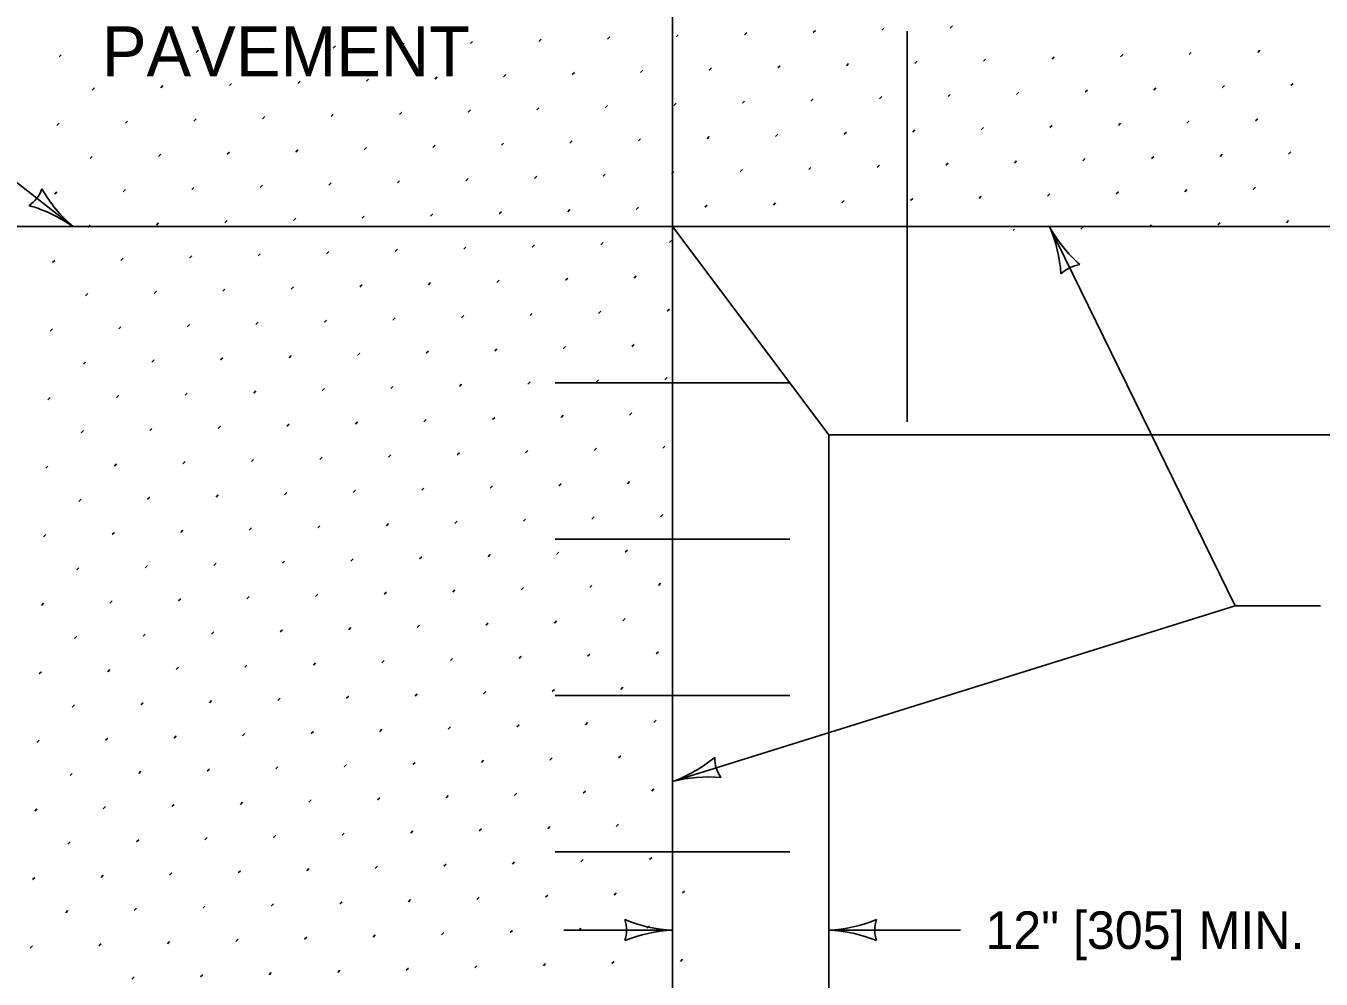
# Model space of a CAD drawing. Extents: x 49991.4 to 50021, y 49987.6 to 50011.4.
# Drawn here: x 50001.323 to 50003.394, y 49990.601 to 49992.125 of the extents above; entities that cross this region are included whole.
import ezdxf

# ---------------------------------------------------------------- set-up
doc = ezdxf.new("R2010")
doc.units = 0
for name, color, linetype in [('Level 1', 7, 'Continuous'), ('Level 10', 7, 'Continuous'), ('Level 2', 7, 'Continuous'), ('Level 3', 7, 'Continuous'), ('Level 4', 7, 'Continuous')]:
    doc.layers.add(name, color=color, linetype=linetype)

msp = doc.modelspace()

# ---------------------------------------------------------------- linework, layer by layer
at = {"layer": 'Level 1'}
for p, q in [((50002.3571, 49991.8039), (50002.3571, 49992.8039)), ((50001.1571, 49991.8039), (50002.3571, 49991.8039)), ((50006.1071, 49991.8039), (50002.3571, 49991.8039)), ((50002.3571, 49991.8039), (50002.3571, 49988.8039)), ((50002.3571, 49991.8039), (50002.6071, 49991.4706)), ((50002.6071, 49991.4706), (50002.6071, 49989.1372)), ((50002.6071, 49991.4706), (50005.8571, 49991.4706))]:
    msp.add_line(p, q, dxfattribs=at)
at = {"layer": 'Level 10'}
for p, q in [((50000.7223, 49992.3318), (50001.3986, 49991.8039)), ((50002.582, 49992.114), (50002.5856, 49992.1175)), ((50002.6916, 49992.1176), (50002.6952, 49992.1211)), ((50002.8013, 49992.1211), (50002.8048, 49992.1246)), ((50002.034, 49992.0963), (50002.0375, 49992.0998)), ((50002.1436, 49992.0998), (50002.1471, 49992.1034)), ((50002.2532, 49992.1034), (50002.2567, 49992.1069)), ((50002.3628, 49992.1069), (50002.3664, 49992.1105)), ((50002.4724, 49992.1105), (50002.476, 49992.114)), ((50001.3763, 49992.075), (50001.3799, 49992.0786)), ((50001.486, 49992.0786), (50001.4895, 49992.0821)), ((50001.5956, 49992.0821), (50001.5991, 49992.0857)), ((50001.7052, 49992.0857), (50001.7087, 49992.0892)), ((50001.8148, 49992.0892), (50001.8183, 49992.0928)), ((50001.9244, 49992.0928), (50001.9279, 49992.0963)), ((50003.0735, 49992.0752), (50003.077, 49992.0787)), ((50003.1831, 49992.0787), (50003.1866, 49992.0822)), ((50003.2927, 49992.0822), (50003.2963, 49992.0858)), ((50002.4159, 49992.0539), (50002.4194, 49992.0574)), ((50002.5255, 49992.0574), (50002.529, 49992.061)), ((50002.6351, 49992.061), (50002.6386, 49992.0645)), ((50002.7447, 49992.0645), (50002.7482, 49992.0681)), ((50002.8543, 49992.0681), (50002.8578, 49992.0716)), ((50002.9639, 49992.0716), (50002.9674, 49992.0751)), ((50001.7582, 49992.0326), (50001.7617, 49992.0362)), ((50001.8678, 49992.0362), (50001.8713, 49992.0397)), ((50001.9774, 49992.0397), (50001.981, 49992.0433)), ((50002.087, 49992.0433), (50002.0906, 49992.0468)), ((50002.1966, 49992.0468), (50002.2002, 49992.0503)), ((50002.3062, 49992.0504), (50002.3098, 49992.0539)), ((50001.4294, 49992.022), (50001.4329, 49992.0255)), ((50001.539, 49992.0256), (50001.5425, 49992.0291)), ((50001.6486, 49992.0291), (50001.6521, 49992.0326)), ((50002.7977, 49992.0115), (50002.8012, 49992.015)), ((50002.9073, 49992.015), (50002.9109, 49992.0186)), ((50003.0169, 49992.0186), (50003.0205, 49992.0221)), ((50003.1265, 49992.0221), (50003.1301, 49992.0257)), ((50003.2361, 49992.0257), (50003.2397, 49992.0292)), ((50003.3458, 49992.0292), (50003.3493, 49992.0327)), ((50002.1401, 49991.9902), (50002.1436, 49991.9938)), ((50002.2497, 49991.9938), (50002.2532, 49991.9973)), ((50002.3593, 49991.9973), (50002.3628, 49992.0009)), ((50002.4689, 49992.0009), (50002.4724, 49992.0044)), ((50002.5785, 49992.0044), (50002.582, 49992.0079)), ((50002.6881, 49992.0079), (50002.6916, 49992.0115)), ((50001.4824, 49991.969), (50001.4859, 49991.9725)), ((50001.592, 49991.9725), (50001.5956, 49991.9761)), ((50001.7016, 49991.9761), (50001.7052, 49991.9796)), ((50001.8112, 49991.9796), (50001.8148, 49991.9831)), ((50001.9208, 49991.9831), (50001.9244, 49991.9867)), ((50002.0305, 49991.9867), (50002.034, 49991.9902)), ((50003.1796, 49991.9691), (50003.1831, 49991.9726)), ((50003.2892, 49991.9726), (50003.2927, 49991.9762)), ((50001.3728, 49991.9654), (50001.3763, 49991.969)), ((50002.6315, 49991.9514), (50002.6351, 49991.9549)), ((50002.7411, 49991.9549), (50002.7447, 49991.9584)), ((50002.8507, 49991.9585), (50002.8543, 49991.962)), ((50002.9604, 49991.962), (50002.9639, 49991.9655)), ((50003.07, 49991.9655), (50003.0735, 49991.9691)), ((50001.9739, 49991.9301), (50001.9774, 49991.9337)), ((50002.0835, 49991.9337), (50002.087, 49991.9372)), ((50002.1931, 49991.9372), (50002.1966, 49991.9407)), ((50002.3027, 49991.9407), (50002.3062, 49991.9443)), ((50002.4123, 49991.9443), (50002.4158, 49991.9478)), ((50002.5219, 49991.9478), (50002.5255, 49991.9514)), ((50001.4258, 49991.9124), (50001.4294, 49991.9159)), ((50001.5354, 49991.9159), (50001.539, 49991.9195)), ((50001.6451, 49991.9195), (50001.6486, 49991.923)), ((50001.7547, 49991.923), (50001.7582, 49991.9266)), ((50001.8643, 49991.9266), (50001.8678, 49991.9301)), ((50003.0134, 49991.909), (50003.0169, 49991.9125)), ((50003.123, 49991.9125), (50003.1265, 49991.916)), ((50003.2326, 49991.9161), (50003.2361, 49991.9196)), ((50003.3422, 49991.9196), (50003.3457, 49991.9231)), ((50002.3557, 49991.8877), (50002.3593, 49991.8912)), ((50002.4653, 49991.8913), (50002.4689, 49991.8948)), ((50002.575, 49991.8948), (50002.5785, 49991.8983)), ((50002.6846, 49991.8983), (50002.6881, 49991.9019)), ((50002.7942, 49991.9019), (50002.7977, 49991.9054)), ((50002.9038, 49991.9054), (50002.9073, 49991.909)), ((50001.6981, 49991.8665), (50001.7016, 49991.87)), ((50001.8077, 49991.87), (50001.8112, 49991.8735)), ((50001.9173, 49991.8735), (50001.9208, 49991.8771)), ((50002.0269, 49991.8771), (50002.0304, 49991.8806)), ((50002.1365, 49991.8806), (50002.1401, 49991.8842)), ((50002.2461, 49991.8842), (50002.2497, 49991.8877)), ((50001.3693, 49991.8558), (50001.3728, 49991.8594)), ((50001.4789, 49991.8594), (50001.4824, 49991.8629)), ((50001.5885, 49991.8629), (50001.592, 49991.8664)), ((50002.7376, 49991.8453), (50002.7411, 49991.8488)), ((50002.8472, 49991.8488), (50002.8507, 49991.8524)), ((50002.9568, 49991.8524), (50002.9603, 49991.8559)), ((50003.0664, 49991.8559), (50003.07, 49991.8595)), ((50003.176, 49991.8595), (50003.1796, 49991.863)), ((50003.2856, 49991.863), (50003.2892, 49991.8666)), ((50002.0799, 49991.8241), (50002.0835, 49991.8276)), ((50002.1896, 49991.8276), (50002.1931, 49991.8311)), ((50002.2992, 49991.8311), (50002.3027, 49991.8347)), ((50002.4088, 49991.8347), (50002.4123, 49991.8382)), ((50002.5184, 49991.8382), (50002.5219, 49991.8418)), ((50002.628, 49991.8418), (50002.6315, 49991.8453)), ((50001.5319, 49991.8063), (50001.5354, 49991.8099)), ((50001.6415, 49991.8099), (50001.645, 49991.8134)), ((50001.7511, 49991.8134), (50001.7547, 49991.817)), ((50001.8607, 49991.817), (50001.8643, 49991.8205)), ((50001.9703, 49991.8205), (50001.9739, 49991.824)), ((50003.2291, 49991.8064), (50003.2326, 49991.81)), ((50003.3387, 49991.81), (50003.3422, 49991.8135)), ((50001.4223, 49991.8028), (50001.4258, 49991.8063)), ((50002.9019, 49991.7974), (50002.9038, 49991.7994)), ((50003.0098, 49991.7994), (50003.0134, 49991.8029)), ((50003.1195, 49991.8029), (50003.123, 49991.8064)), ((50001.9138, 49991.7639), (50001.9173, 49991.7675)), ((50002.0234, 49991.7675), (50002.0269, 49991.771)), ((50002.133, 49991.771), (50002.1365, 49991.7746)), ((50002.2426, 49991.7746), (50002.2461, 49991.7781)), ((50002.3522, 49991.7781), (50002.3557, 49991.7816)), ((50001.3657, 49991.7462), (50001.3693, 49991.7498)), ((50001.4753, 49991.7498), (50001.4789, 49991.7533)), ((50001.5849, 49991.7533), (50001.5885, 49991.7568)), ((50001.6945, 49991.7568), (50001.6981, 49991.7604)), ((50001.8041, 49991.7604), (50001.8077, 49991.7639)), ((50002.2956, 49991.7215), (50002.2992, 49991.7251)), ((50001.638, 49991.7003), (50001.6415, 49991.7038)), ((50001.7476, 49991.7038), (50001.7511, 49991.7073)), ((50001.8572, 49991.7074), (50001.8607, 49991.7109)), ((50001.9668, 49991.7109), (50001.9703, 49991.7144)), ((50002.0764, 49991.7144), (50002.0799, 49991.718)), ((50002.186, 49991.718), (50002.1895, 49991.7215)), ((50001.4187, 49991.6932), (50001.4223, 49991.6967)), ((50001.5284, 49991.6967), (50001.5319, 49991.7003)), ((50002.1294, 49991.6614), (50002.133, 49991.6649)), ((50002.239, 49991.665), (50002.2426, 49991.6685)), ((50002.3486, 49991.6685), (50002.3522, 49991.672)), ((50001.4718, 49991.6402), (50001.4753, 49991.6437)), ((50001.5814, 49991.6437), (50001.5849, 49991.6472)), ((50001.691, 49991.6472), (50001.6945, 49991.6508)), ((50001.8006, 49991.6508), (50001.8041, 49991.6543)), ((50001.9102, 49991.6543), (50001.9138, 49991.6579)), ((50002.0198, 49991.6579), (50002.0234, 49991.6614)), ((50001.3622, 49991.6366), (50001.3657, 49991.6401)), ((50001.8536, 49991.5977), (50001.8572, 49991.6013)), ((50001.9632, 49991.6013), (50001.9668, 49991.6048)), ((50002.0729, 49991.6048), (50002.0764, 49991.6084)), ((50002.1825, 49991.6084), (50002.186, 49991.6119)), ((50002.2921, 49991.6119), (50002.2956, 49991.6155)), ((50001.4152, 49991.5836), (50001.4187, 49991.5871)), ((50001.5248, 49991.5871), (50001.5283, 49991.5907)), ((50001.6344, 49991.5907), (50001.638, 49991.5942)), ((50001.744, 49991.5942), (50001.7476, 49991.5977)), ((50002.2355, 49991.5553), (50002.239, 49991.5589)), ((50002.3451, 49991.5589), (50002.3486, 49991.5624)), ((50001.5778, 49991.5341), (50001.5814, 49991.5376)), ((50001.6875, 49991.5376), (50001.691, 49991.5412)), ((50001.7971, 49991.5412), (50001.8006, 49991.5447)), ((50001.9067, 49991.5447), (50001.9102, 49991.5483)), ((50002.0163, 49991.5483), (50002.0198, 49991.5518)), ((50002.1259, 49991.5518), (50002.1294, 49991.5553)), ((50001.3586, 49991.527), (50001.3622, 49991.5305)), ((50001.4682, 49991.5305), (50001.4718, 49991.5341)), ((50002.0693, 49991.4952), (50002.0728, 49991.4988)), ((50002.1789, 49991.4988), (50002.1825, 49991.5023)), ((50002.2885, 49991.5023), (50002.2921, 49991.5058)), ((50001.4117, 49991.474), (50001.4152, 49991.4775)), ((50001.5213, 49991.4775), (50001.5248, 49991.481)), ((50001.6309, 49991.4811), (50001.6344, 49991.4846)), ((50001.7405, 49991.4846), (50001.744, 49991.4881)), ((50001.8501, 49991.4881), (50001.8536, 49991.4917)), ((50001.9597, 49991.4917), (50001.9632, 49991.4952)), ((50001.7935, 49991.4316), (50001.7971, 49991.4351)), ((50001.9031, 49991.4351), (50001.9067, 49991.4386)), ((50002.0127, 49991.4386), (50002.0163, 49991.4422)), ((50002.1223, 49991.4422), (50002.1259, 49991.4457)), ((50002.232, 49991.4457), (50002.2355, 49991.4493)), ((50002.3416, 49991.4493), (50002.3451, 49991.4528)), ((50001.3551, 49991.4174), (50001.3586, 49991.4209)), ((50001.4647, 49991.4209), (50001.4682, 49991.4245)), ((50001.5743, 49991.4245), (50001.5778, 49991.428)), ((50001.6839, 49991.428), (50001.6874, 49991.4316)), ((50002.1754, 49991.3892), (50002.1789, 49991.3927)), ((50002.285, 49991.3927), (50002.2885, 49991.3962)), ((50001.6273, 49991.3714), (50001.6309, 49991.375)), ((50001.7369, 49991.375), (50001.7405, 49991.3785)), ((50001.8466, 49991.3785), (50001.8501, 49991.3821)), ((50001.9562, 49991.3821), (50001.9597, 49991.3856)), ((50002.0658, 49991.3856), (50002.0693, 49991.3892)), ((50001.4081, 49991.3644), (50001.4117, 49991.3679)), ((50001.5177, 49991.3679), (50001.5213, 49991.3714)), ((50002.0092, 49991.329), (50002.0127, 49991.3326)), ((50002.1188, 49991.3326), (50002.1223, 49991.3361)), ((50002.2284, 49991.3361), (50002.2319, 49991.3397)), ((50002.338, 49991.3397), (50002.3416, 49991.3432)), ((50001.3515, 49991.3078), (50001.3551, 49991.3113)), ((50001.4612, 49991.3113), (50001.4647, 49991.3149)), ((50001.5708, 49991.3149), (50001.5743, 49991.3184)), ((50001.6804, 49991.3184), (50001.6839, 49991.3219)), ((50001.79, 49991.322), (50001.7935, 49991.3255)), ((50001.8996, 49991.3255), (50001.9031, 49991.329)), ((50001.7334, 49991.2654), (50001.7369, 49991.2689)), ((50001.843, 49991.2689), (50001.8465, 49991.2725)), ((50001.9526, 49991.2725), (50001.9562, 49991.276)), ((50002.0622, 49991.276), (50002.0658, 49991.2795)), ((50002.1718, 49991.2795), (50002.1754, 49991.2831)), ((50002.2814, 49991.2831), (50002.285, 49991.2866)), ((50001.4046, 49991.2548), (50001.4081, 49991.2583)), ((50001.5142, 49991.2583), (50001.5177, 49991.2618)), ((50001.6238, 49991.2618), (50001.6273, 49991.2654)), ((50002.2249, 49991.2265), (50002.2284, 49991.2301)), ((50002.3345, 49991.2301), (50002.338, 49991.2336)), ((50001.5672, 49991.2053), (50001.5708, 49991.2088)), ((50001.6768, 49991.2088), (50001.6804, 49991.2123)), ((50001.7864, 49991.2123), (50001.79, 49991.2159)), ((50001.896, 49991.2159), (50001.8996, 49991.2194)), ((50002.0057, 49991.2194), (50002.0092, 49991.223)), ((50002.1153, 49991.223), (50002.1188, 49991.2265)), ((50001.348, 49991.1982), (50001.3515, 49991.2017)), ((50001.4576, 49991.2017), (50001.4611, 49991.2053)), ((50003.2566, 49991.1975), (50003.393, 49991.1975)), ((50001.9491, 49991.1629), (50001.9526, 49991.1664)), ((50002.0587, 49991.1664), (50002.0622, 49991.1699)), ((50002.1683, 49991.1699), (50002.1718, 49991.1735)), ((50002.2779, 49991.1735), (50002.2814, 49991.177)), ((50001.401, 49991.1451), (50001.4046, 49991.1487)), ((50001.5106, 49991.1487), (50001.5142, 49991.1522)), ((50001.6203, 49991.1522), (50001.6238, 49991.1558)), ((50001.7299, 49991.1558), (50001.7334, 49991.1593)), ((50001.8395, 49991.1593), (50001.843, 49991.1628)), ((50002.3309, 49991.1205), (50002.3345, 49991.124)), ((50001.6733, 49991.0992), (50001.6768, 49991.1027)), ((50001.7829, 49991.1027), (50001.7864, 49991.1063)), ((50001.8925, 49991.1063), (50001.896, 49991.1098)), ((50002.0021, 49991.1098), (50002.0056, 49991.1134)), ((50002.1117, 49991.1134), (50002.1153, 49991.1169)), ((50002.2213, 49991.1169), (50002.2249, 49991.1204)), ((50001.3445, 49991.0886), (50001.348, 49991.0921)), ((50001.4541, 49991.0921), (50001.4576, 49991.0956)), ((50001.5637, 49991.0957), (50001.5672, 49991.0992)), ((50002.1648, 49991.0603), (50002.1683, 49991.0639)), ((50002.2744, 49991.0639), (50002.2779, 49991.0674)), ((50001.5071, 49991.0391), (50001.5106, 49991.0426)), ((50001.6167, 49991.0426), (50001.6202, 49991.0462)), ((50001.7263, 49991.0462), (50001.7299, 49991.0497)), ((50001.8359, 49991.0497), (50001.8395, 49991.0532)), ((50001.9455, 49991.0532), (50001.9491, 49991.0568)), ((50002.0551, 49991.0568), (50002.0587, 49991.0603)), ((50001.3975, 49991.0355), (50001.401, 49991.0391)), ((50001.889, 49990.9967), (50001.8925, 49991.0002)), ((50001.9986, 49991.0002), (50002.0021, 49991.0037)), ((50002.1082, 49991.0038), (50002.1117, 49991.0073)), ((50002.2178, 49991.0073), (50002.2213, 49991.0108)), ((50002.3274, 49991.0108), (50002.3309, 49991.0144)), ((50001.3409, 49990.979), (50001.3445, 49990.9825)), ((50001.4505, 49990.9825), (50001.4541, 49990.986)), ((50001.5601, 49990.986), (50001.5637, 49990.9896)), ((50001.6697, 49990.9896), (50001.6733, 49990.9931)), ((50001.7794, 49990.9931), (50001.7829, 49990.9967)), ((50002.2708, 49990.9543), (50002.2744, 49990.9578)), ((50001.7228, 49990.9366), (50001.7263, 49990.9401)), ((50001.8324, 49990.9401), (50001.8359, 49990.9436)), ((50001.942, 49990.9436), (50001.9455, 49990.9472)), ((50002.0516, 49990.9472), (50002.0551, 49990.9507)), ((50002.1612, 49990.9507), (50002.1647, 49990.9543)), ((50001.3939, 49990.9259), (50001.3975, 49990.9295)), ((50001.5036, 49990.9295), (50001.5071, 49990.933)), ((50001.6132, 49990.933), (50001.6167, 49990.9365)), ((50002.1046, 49990.8941), (50002.1082, 49990.8977)), ((50002.2142, 49990.8977), (50002.2178, 49990.9012)), ((50002.3239, 49990.9012), (50002.3274, 49990.9048)), ((50001.447, 49990.8729), (50001.4505, 49990.8764)), ((50001.5566, 49990.8764), (50001.5601, 49990.88)), ((50001.6662, 49990.88), (50001.6697, 49990.8835)), ((50001.7758, 49990.8835), (50001.7793, 49990.8871)), ((50001.8854, 49990.8871), (50001.889, 49990.8906)), ((50001.995, 49990.8906), (50001.9986, 49990.8941)), ((50001.3374, 49990.8693), (50001.3409, 49990.8729)), ((50001.8288, 49990.8305), (50001.8324, 49990.834)), ((50001.9385, 49990.834), (50001.942, 49990.8376)), ((50002.0481, 49990.8376), (50002.0516, 49990.8411)), ((50002.1577, 49990.8411), (50002.1612, 49990.8447)), ((50002.2673, 49990.8447), (50002.2708, 49990.8482)), ((50001.3904, 49990.8163), (50001.3939, 49990.8199)), ((50001.5, 49990.8199), (50001.5036, 49990.8234)), ((50001.6096, 49990.8234), (50001.6132, 49990.8269)), ((50001.7192, 49990.8269), (50001.7228, 49990.8305)), ((50002.3203, 49990.7916), (50002.3238, 49990.7952)), ((50001.6627, 49990.7704), (50001.6662, 49990.7739)), ((50001.7723, 49990.7739), (50001.7758, 49990.7774)), ((50001.8819, 49990.7775), (50001.8854, 49990.781)), ((50001.9915, 49990.781), (50001.995, 49990.7845)), ((50002.1011, 49990.7845), (50002.1046, 49990.7881)), ((50002.2107, 49990.7881), (50002.2142, 49990.7916)), ((50001.3338, 49990.7597), (50001.3374, 49990.7633)), ((50001.4434, 49990.7633), (50001.447, 49990.7668)), ((50001.553, 49990.7668), (50001.5566, 49990.7704)), ((50002.0445, 49990.728), (50002.0481, 49990.7315)), ((50002.1541, 49990.7315), (50002.1577, 49990.735)), ((50002.2637, 49990.735), (50002.2673, 49990.7386)), ((50002.3733, 49990.7386), (50002.3761, 49990.7413)), ((50001.3869, 49990.7067), (50001.3904, 49990.7102)), ((50001.4965, 49990.7103), (50001.5, 49990.7138)), ((50001.6061, 49990.7138), (50001.6096, 49990.7173)), ((50001.7157, 49990.7173), (50001.7192, 49990.7209)), ((50001.8253, 49990.7209), (50001.8288, 49990.7244)), ((50001.9349, 49990.7244), (50001.9384, 49990.728)), ((50001.7687, 49990.6643), (50001.7723, 49990.6678)), ((50001.8783, 49990.6678), (50001.8819, 49990.6714)), ((50001.9879, 49990.6714), (50001.9915, 49990.6749)), ((50002.0975, 49990.6749), (50002.1011, 49990.6785)), ((50002.2072, 49990.6785), (50002.2107, 49990.682)), ((50002.3168, 49990.682), (50002.3203, 49990.6856)), ((50001.3303, 49990.6501), (50001.3338, 49990.6537)), ((50001.4399, 49990.6537), (50001.4434, 49990.6572)), ((50001.5495, 49990.6572), (50001.553, 49990.6608)), ((50001.6591, 49990.6608), (50001.6627, 49990.6643)), ((50002.2602, 49990.6254), (50002.2637, 49990.629)), ((50002.3698, 49990.629), (50002.3733, 49990.6325)), ((50001.6025, 49990.6042), (50001.6061, 49990.6077)), ((50001.7121, 49990.6077), (50001.7157, 49990.6113)), ((50001.8218, 49990.6113), (50001.8253, 49990.6148)), ((50001.9314, 49990.6148), (50001.9349, 49990.6183)), ((50002.041, 49990.6184), (50002.0445, 49990.6219)), ((50002.1506, 49990.6219), (50002.1541, 49990.6254)), ((50001.4929, 49990.6006), (50001.4965, 49990.6042))]:
    msp.add_line(p, q, dxfattribs=at)
at = {"layer": 'Level 3'}
for p, q in [((50002.9598, 49991.8039), (50003.2566, 49991.1975)), ((50002.3571, 49990.9164), (50003.2566, 49991.1975)), ((50002.1836, 49990.6789), (50002.3571, 49990.6789)), ((50002.6071, 49990.6789), (50002.8174, 49990.6789))]:
    msp.add_line(p, q, dxfattribs=at)
for centre, radius, start, end in [((50001.2975, 49991.8828), 0.0548, 304.1631, 339.8855), ((50001.5425, 49991.9734), 0.2223, 209.4803, 229.6638), ((50001.2644, 49991.6134), 0.233, 54.8516, 74.1015), ((50002.7563, 49991.7145), 0.2223, 3.5339, 23.7174), ((50003.1638, 49991.9165), 0.233, 208.9052, 228.155), ((50003.0162, 49991.6887), 0.0548, 98.2167, 133.939), ((50002.2767, 49991.1351), 0.233, 290.1822, 309.4321), ((50002.4794, 49990.9546), 0.0548, 179.4937, 215.2161), ((50002.4146, 49990.7016), 0.2223, 84.8109, 104.9944), ((50002.3662, 49990.901), 0.2223, 247.4572, 267.6407), ((50002.2288, 49990.6789), 0.0548, 342.14, 17.8624), ((50002.5956, 49990.9116), 0.233, 272.8285, 292.0784), ((50002.7353, 49990.6789), 0.0548, 162.14, 197.8624), ((50002.3686, 49990.4462), 0.233, 92.8285, 112.0784), ((50002.5979, 49990.4568), 0.2223, 67.4572, 87.6407)]:
    msp.add_arc(centre, radius, start, end, dxfattribs=at)
at = {"layer": 'Level 4'}
for p, q in [((50002.7321, 49992.1164), (50002.7321, 49991.4914)), ((50002.1696, 49991.5539), (50002.5446, 49991.5539)), ((50002.1696, 49991.3039), (50002.5446, 49991.3039)), ((50002.1696, 49991.0539), (50002.5446, 49991.0539)), ((50002.1696, 49990.8039), (50002.5446, 49990.8039))]:
    msp.add_line(p, q, dxfattribs=at)

# ---------------------------------------------------------------- texts
at = {"layer": 'Level 2'}
for s, height, p in [('PAVEMENT', 0.08, (50001.4448, 49992.0439)), ('12" [305] MIN.', 0.06, (50002.8574, 49990.6489))]:
    msp.add_text(s, height=height, dxfattribs=at).set_placement(p)

doc.saveas('drawing.dxf')
